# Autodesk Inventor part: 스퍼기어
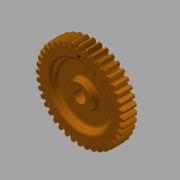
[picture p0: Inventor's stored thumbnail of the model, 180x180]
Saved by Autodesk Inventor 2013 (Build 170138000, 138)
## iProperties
Created: 2019-01
Part Number: 스퍼기어
Material: 알루미늄 6061
Document SubType Name: Modeling
Designer: mduedu
Density: 2.71 g/cm^3
Mass: 157.226 g
Surface Area: 186.47 cm^2
Volume: 58.017 cm^3
Author: mduedu
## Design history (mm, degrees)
sketch "스케치1"
  geometry: C1 r 37.5 at (0, 0); C2 r 40 at (0, 0); C3 r 42 at (0, 0); 1 further point
  constraints: 3 centre point, 3 coincident
  dimensions: "d0" = 75 diameter of C1; "d2" = 80 diameter of C2; "d3" = 84 diameter of C3
extrude "돌출1" new body sketch "스케치1" distance "d4" = 14; taper "d5" = 0 deg
sketch "스케치2"
  geometry: L1 (0, 0)-(-42, 0); L2 (0, 0)-(0, 42); L3 (-0.57, 0)-(-0.57, 41.996); L4 (-1.57, 0)-(-1.57, 39.969); L5 (-2.07, 0)-(-2.07, 37.443); A1 r 42 centre (0, 0) between (-42, 0) and (0, 42) reference; A2 r 9.223 centre (7.138, 36.933) between (-0.57, 41.996) and (-2.07, 37.443); A3 r 9.223 centre (-7.138, 36.933) between (2.07, 37.443) and (0.57, 41.996); A4 r 37.5 centre (0, 0) between (2.07, 37.443) and (-2.07, 37.443); A5 r 42 centre (0, 0) between (0.57, 41.996) and (-0.57, 41.996); 2 further points
  constraints: 12 point on circle, 10 end point, 4 centre point, 3 parallel, 3 symmetric about line, 2 coincident, 1 horizontal, 1 perpendicular, 5 other
  dimensions: "d6" = 0.5 distance between parallel lines of L4 L5; "d8" = 1 distance between parallel lines of L3 L4; "d9" = 1.57 distance between parallel lines of L2 L4
extrude "돌출2" join sketch "스케치2" stored distance "d10" = 14; taper "d11" = 0 deg
chamfer "모따기1" distance "d12" = 1; stored, may be unused: second distance "d13" = 2, angle "d14" = 45 deg
fillet "모깎기1" dims "d15" = 0.5
sketch "스케치3"
  geometry: C1 r 11 at (0, 0); 1 further point
  constraints: 1 centre point, 1 coincident
  dimensions: "d19" = 22 diameter of C1
extrude "돌출3" join sketch "스케치3" distance "d20" = 7; taper "d21" = 0 deg
fillet "모깎기2" dims "d22" = 3
sketch "스케치4"
  geometry: C1 r 11 at (0, 0); C2 r 27.5 at (0, 0); 1 further point
  constraints: 2 centre point, 2 coincident
  dimensions: "d23" = 22 diameter of C1; "d24" = 55 diameter of C2
extrude "돌출4" cut sketch "스케치4" distance "d25" = 6; taper "d26" = 0 deg
fillet "모깎기3" dims "d27" = 3
sketch "스케치5" dims "d28" = 66
  geometry: C1 r 1.5 at (0, 33); 2 further points
  constraints: 2 vertical alignment, 1 centre point, 1 coincident, 2 other
  dimensions: "d29" = 3 diameter of C1
extrude "돌출5" join sketch "스케치5" distance "d30" = 0.5; taper "d31" = 0 deg
sketch "스케치6"
  geometry: L1 (-2, 5.657)-(2, 5.657); L2 (2, 5.657)-(2, 7.8); L3 (2, 7.8)-(-2, 7.8); L4 (-2, 7.8)-(-2, 5.657); A1 r 6 centre (0, 0) between (-2, 5.657) and (2, 5.657); 1 further point
  constraints: 8 end point, 2 parallel, 2 point on circle, 1 centre point, 1 coincident, 1 horizontal, 1 perpendicular
  dimensions: "d32" = 13.8 dimension on A1 L3; "d34" = 4 distance of L2.end L3.end; "d35" = 12 diameter of A1
extrude "돌출6" cut sketch "스케치6" stored distance "d36" = 0.5; taper "d37" = 0 deg
chamfer "모따기2" distance "d38" = 1; stored, may be unused: second distance "d39" = 2, angle "d40" = 45 deg
node "솔리드1"
pattern_circular "원형 패턴1" dims "d17" = 360 deg
